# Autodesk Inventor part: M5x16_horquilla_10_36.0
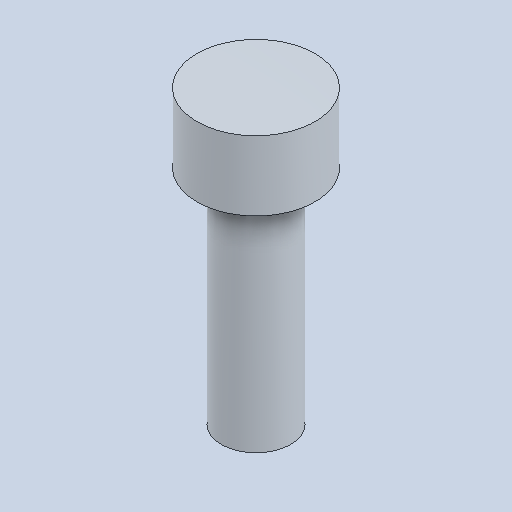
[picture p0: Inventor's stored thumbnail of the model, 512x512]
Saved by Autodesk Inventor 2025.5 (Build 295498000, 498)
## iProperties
Created: 2026-10
Part Number: M5x16_horquilla_10_36.0
Material: Genérico
Document SubType Name: Modeling
Designer: Luis M
Density: 1 g/cm^3
Appearance: Valor por defecto
Author: Luis M
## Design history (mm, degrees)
feature "Base1"
node "Sólido1"
